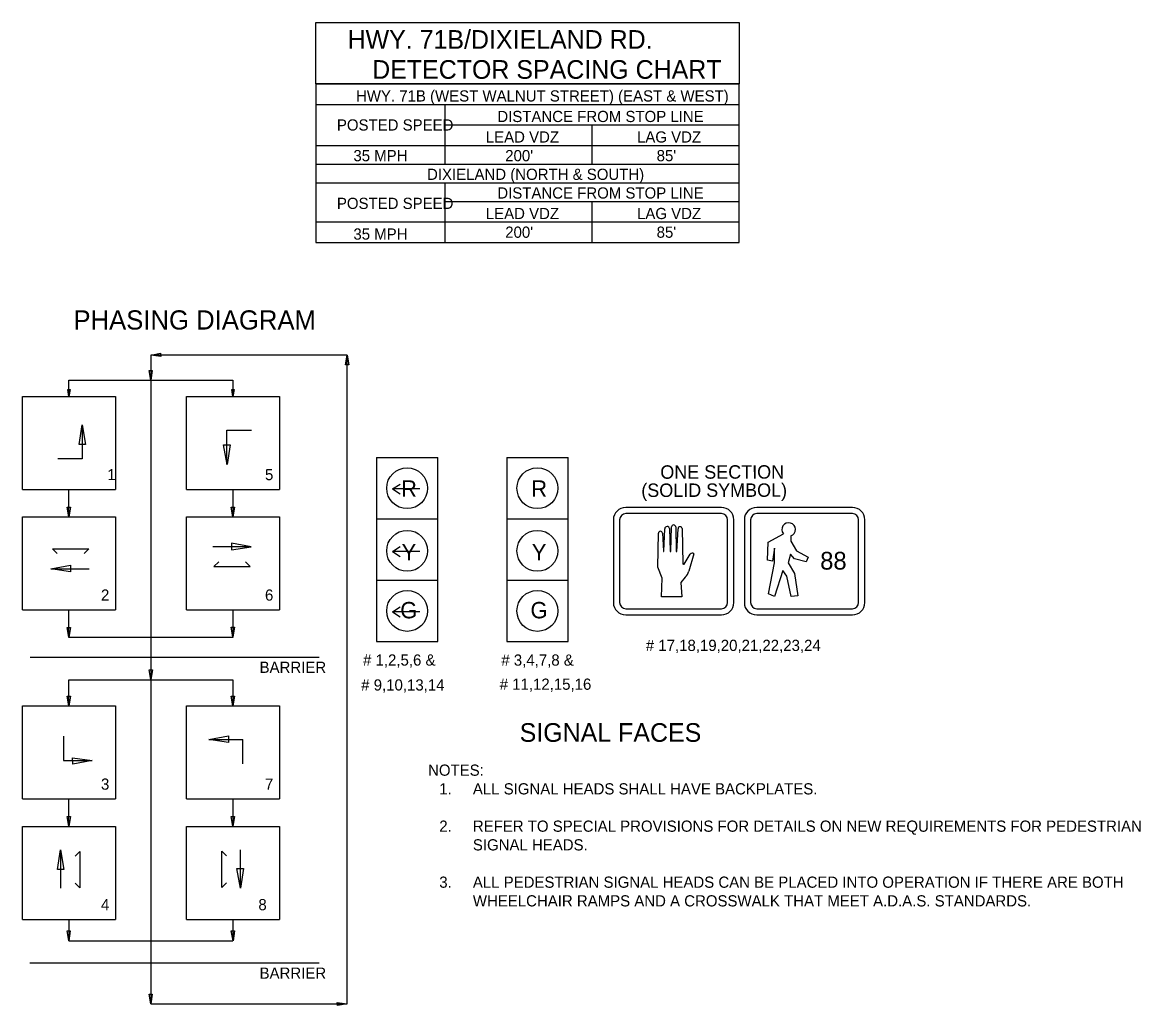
# Model space of a CAD drawing. Extents: x -15.7 to 19.3, y -1.4 to 10.8.
# Drawn here: x -8.42 to -0.43, y 3.54 to 10.56 of the extents above; entities that cross this region are included whole.
import ezdxf

# ---------------------------------------------------------------- set-up
doc = ezdxf.new("R2010")
doc.units = 0
for name, color, linetype in [('$', 7, 'Continuous'), ('base', 7, 'Continuous'), ('PHASE', 7, 'Continuous'), ('T_Drafting', 7, 'Continuous'), ('TBLBDR', 7, 'Continuous'), ('TBLLINE', 7, 'Continuous'), ('TBLTEXT', 7, 'Continuous'), ('TITEXT', 7, 'Continuous')]:
    doc.layers.add(name, color=color, linetype=linetype)

msp = doc.modelspace()

# ---------------------------------------------------------------- linework, layer by layer
at = {"layer": '$'}
for p, q in [((-6.1, 3.5529), (-6.1, 8.1869)), ((-8.0877, 8.0067), (-6.9162, 8.0067)), ((-6.7865, 6.8174), (-7.0596, 6.8174)), ((-8.2155, 6.6601), (-7.9423, 6.6601)), ((-8.1258, 5.4654), (-8.1258, 5.2903)), ((-7.087, 5.4413), (-6.8438, 5.4413)), ((-6.8438, 5.2668), (-6.8438, 5.4413)), ((-8.1258, 5.2903), (-7.9208, 5.2903)), ((-8.0877, 4.156), (-8.0877, 4.0032)), ((-7.5019, 3.8369), (-7.5019, 3.5529)), ((-7.5019, 3.5529), (-6.1, 3.5529))]:
    msp.add_line(p, q, dxfattribs=at)
for points in [[(-6.1, 8.1869), (-7.5019, 8.1869), (-7.5019, 8.0067)], [(-8.0877, 7.8919), (-8.0877, 8.0067)], [(-6.9162, 8.0067), (-6.9162, 7.8919)], [(-7.9921, 7.6882), (-7.9921, 7.4449), (-8.1666, 7.4449)], [(-6.9587, 7.4064), (-6.9587, 7.6496), (-6.7842, 7.6496)], [(-8.0877, 7.0313), (-8.0877, 7.2274)], [(-6.9162, 7.2274), (-6.9162, 7.0313)], [(-6.9162, 6.3668), (-6.9162, 6.1708), (-8.0877, 6.1708), (-8.0877, 6.3668)], [(-7.5019, 6.1708), (-7.5019, 5.8683)], [(-8.0877, 5.6811), (-8.0877, 5.8683), (-6.9162, 5.8683), (-6.9162, 5.6811)], [(-8.0877, 4.8205), (-8.0877, 5.0166)], [(-6.9162, 5.0166), (-6.9162, 4.8205)], [(-8.1485, 4.6534), (-8.1485, 4.3803)], [(-6.8609, 4.3803), (-6.8609, 4.6534)]]:
    msp.add_lwpolyline(points, dxfattribs=at)
at = {"layer": 'PHASE'}
for p, q in [((-5.7765, 7.2306), (-5.7203, 7.2661)), ((-5.5814, 7.2306), (-5.7765, 7.2306)), ((-5.7765, 7.2306), (-5.7203, 7.1951)), ((-5.7765, 6.7833), (-5.7203, 6.8188)), ((-5.5814, 6.7833), (-5.7765, 6.7833)), ((-5.7765, 6.7833), (-5.7203, 6.7479)), ((-5.7765, 6.3539), (-5.7203, 6.3894)), ((-5.5814, 6.3539), (-5.7765, 6.3539)), ((-5.7765, 6.3539), (-5.7203, 6.3185))]:
    msp.add_line(p, q, dxfattribs=at)
for points in [[(-3.7876, 6.7858), (-3.783, 6.9601)], [(-3.7526, 6.9604), (-3.7487, 6.7851)], [(-3.6842, 6.6007), (-3.7158, 6.5618), (-3.7079, 6.4594), (-3.8536, 6.4594), (-3.8485, 6.5934), (-3.8812, 6.6722), (-3.8761, 6.9146)], [(-3.8479, 6.915), (-3.8406, 6.7857)], [(-3.8366, 6.7857), (-3.8309, 6.9468)], [(-3.7965, 6.9479), (-3.792, 6.7857)], [(-3.7445, 6.7851), (-3.7358, 6.9469)], [(-3.7071, 6.9479), (-3.7009, 6.6963)], [(-3.046, 6.462), (-3.0897, 6.4817), (-3.0475, 6.7019), (-3.0457, 6.8071), (-3.0612, 6.7159), (-3.0976, 6.7215), (-3.0915, 6.8514), (-2.9833, 6.91)], [(-2.9291, 6.8949), (-2.93, 6.8585), (-2.8894, 6.7877), (-2.8075, 6.7434), (-2.8195, 6.7105), (-2.9031, 6.7317), (-2.9325, 6.7647), (-2.9504, 6.7022), (-2.9048, 6.6275), (-2.881, 6.4671), (-2.9274, 6.4633), (-2.9579, 6.6086), (-2.9879, 6.648), (-3.046, 6.462)], [(-3.6932, 6.6937), (-3.6483, 6.7659)], [(-3.6223, 6.7664), (-3.6582, 6.6436)]]:
    msp.add_lwpolyline(points, dxfattribs=at)
for centre in [(-5.6711, 7.2361), (-4.7408, 7.2361), (-5.6711, 6.7888), (-4.7408, 6.7888), (-5.6711, 6.3594), (-4.7408, 6.3594)]:
    msp.add_circle(centre, 0.1461, dxfattribs=at)
for centre, radius, start, end in [((-3.8136, 6.9451), 0.0174, 9.19884, 174.46931), ((-3.7678, 6.9586), 0.0153, 6.92087, 174.32546), ((-3.7214, 6.9467), 0.0144, 5.08526, 179.16231), ((-2.9456, 6.9406), 0.0486, 289.8249, 219.00652), ((-3.862, 6.9142), 0.0141, 3.29515, 178.19589), ((-3.8386, 6.7857), 0.00202, 181.1546, 359.79185), ((-3.7898, 6.7857), 0.00218, 181.28856, 2.11272), ((-3.7466, 6.7852), 0.00211, 183.88454, 355.84434), ((-3.6351, 6.7562), 0.0164, 38.81604, 143.75147), ((-3.6965, 6.6966), 0.00439, 183.95836, 317.86458), ((-3.7491, 6.6695), 0.0946, 313.34065, 344.09332)]:
    msp.add_arc(centre, radius, start, end, dxfattribs=at)
at = {"layer": 'TBLBDR'}
for p, q in [((-6.3235, 10.1242), (-6.3235, 8.9912)), ((-6.3235, 10.1242), (-3.2992, 10.1242)), ((-6.3235, 10.1242), (-3.2992, 10.1242)), ((-3.2992, 8.9912), (-3.2992, 10.1242)), ((-6.3235, 9.9776), (-3.2992, 9.9776)), ((-6.3235, 9.551), (-3.2992, 9.551)), ((-6.3235, 9.4177), (-3.2992, 9.4177)), ((-6.3235, 8.9912), (-3.2992, 8.9912)), ((-8.4199, 7.8919), (-7.7554, 7.8919)), ((-8.4199, 7.2274), (-8.4199, 7.8919)), ((-7.7554, 7.8919), (-7.7554, 7.2274)), ((-7.2484, 7.8919), (-6.5839, 7.8919)), ((-7.2484, 7.2274), (-7.2484, 7.8919)), ((-6.5839, 7.8919), (-6.5839, 7.2274)), ((-5.8902, 7.4552), (-5.4519, 7.4552)), ((-5.8902, 7.4552), (-5.8902, 6.1402)), ((-5.4519, 6.1402), (-5.4519, 7.4552)), ((-4.96, 7.4552), (-4.5217, 7.4552)), ((-4.96, 7.4552), (-4.96, 6.1402)), ((-4.5217, 6.1402), (-4.5217, 7.4552)), ((-8.4199, 7.2274), (-7.7554, 7.2274)), ((-7.2484, 7.2274), (-6.5839, 7.2274)), ((-8.4199, 7.0313), (-7.7554, 7.0313)), ((-8.4199, 6.3668), (-8.4199, 7.0313)), ((-7.7554, 7.0313), (-7.7554, 6.3668)), ((-7.2484, 6.3668), (-7.2484, 7.0313)), ((-7.2484, 7.0313), (-6.5839, 7.0313)), ((-6.5839, 7.0313), (-6.5839, 6.3668)), ((-5.8902, 7.0169), (-5.4519, 7.0169)), ((-4.96, 7.0169), (-4.5217, 7.0169)), ((-5.8902, 6.5786), (-5.4519, 6.5786)), ((-4.96, 6.5786), (-4.5217, 6.5786)), ((-8.4199, 6.3668), (-7.7554, 6.3668)), ((-7.2484, 6.3668), (-6.5839, 6.3668)), ((-5.8902, 6.1402), (-5.4519, 6.1402)), ((-4.96, 6.1402), (-4.5217, 6.1402)), ((-8.4199, 5.6811), (-7.7554, 5.6811)), ((-8.4199, 5.0166), (-8.4199, 5.6811)), ((-7.7554, 5.6811), (-7.7554, 5.0166)), ((-7.2484, 5.6811), (-6.5839, 5.6811)), ((-7.2484, 5.0166), (-7.2484, 5.6811)), ((-6.5839, 5.6811), (-6.5839, 5.0166)), ((-8.4199, 5.0166), (-7.7554, 5.0166)), ((-7.2484, 5.0166), (-6.5839, 5.0166)), ((-8.4199, 4.156), (-8.4199, 4.8205)), ((-8.4199, 4.8205), (-7.7554, 4.8205)), ((-7.7554, 4.8205), (-7.7554, 4.156)), ((-7.2484, 4.156), (-7.2484, 4.8205)), ((-7.2484, 4.8205), (-6.5839, 4.8205)), ((-6.5839, 4.8205), (-6.5839, 4.156)), ((-8.4199, 4.156), (-7.7554, 4.156)), ((-7.2484, 4.156), (-6.5839, 4.156))]:
    msp.add_line(p, q, dxfattribs=at)
msp.add_lwpolyline([(-6.3235, 10.5631), (-3.2992, 10.5631), (-3.2992, 10.1242), (-6.3235, 10.1242)], close=True, dxfattribs=at)
for points in [[(-3.4256, 7.0985), (-4.1095, 7.0985)], [(-3.4256, 7.0544), (-4.1095, 7.0544)], [(-2.4901, 7.0985), (-3.174, 7.0985)], [(-2.4901, 7.0544), (-3.174, 7.0544)], [(-4.1977, 7.0104), (-4.1977, 6.4196)], [(-4.1536, 7.0104), (-4.1536, 6.4196)], [(-3.3815, 6.4196), (-3.3815, 7.0104)], [(-3.3374, 6.4196), (-3.3374, 7.0104)], [(-3.2622, 7.0104), (-3.2622, 6.4196)], [(-3.2181, 7.0104), (-3.2181, 6.4196)], [(-2.446, 6.4196), (-2.446, 7.0104)], [(-2.4019, 6.4196), (-2.4019, 7.0104)], [(-4.1095, 6.3755), (-3.4256, 6.3755)], [(-4.1095, 6.3314), (-3.4256, 6.3314)], [(-3.174, 6.3755), (-2.4901, 6.3755)], [(-3.174, 6.3314), (-2.4901, 6.3314)]]:
    msp.add_lwpolyline(points, dxfattribs=at)
for centre, radius, start, end in [((-4.1095, 7.0104), 0.0882, 90, 180), ((-4.1095, 7.0104), 0.0441, 90, 180), ((-3.4256, 7.0104), 0.0882, 360, 90), ((-3.4256, 7.0104), 0.0441, 360, 90), ((-3.174, 7.0104), 0.0882, 90, 180), ((-3.174, 7.0104), 0.0441, 90, 180), ((-2.4901, 7.0104), 0.0882, 360, 90), ((-2.4901, 7.0104), 0.0441, 360, 90), ((-4.1095, 6.4196), 0.0882, 180, 270), ((-4.1095, 6.4196), 0.0441, 180, 270), ((-3.4256, 6.4196), 0.0882, 270, 360), ((-3.4256, 6.4196), 0.0441, 270, 360), ((-3.174, 6.4196), 0.0882, 180, 270), ((-3.174, 6.4196), 0.0441, 180, 270), ((-2.4901, 6.4196), 0.0882, 270, 360), ((-2.4901, 6.4196), 0.0441, 270, 360)]:
    msp.add_arc(centre, radius, start, end, dxfattribs=at)
at = {"layer": 'TBLLINE'}
for p, q in [((-5.4016, 9.9776), (-5.4016, 9.551)), ((-5.4016, 9.8309), (-3.2992, 9.8309)), ((-4.3504, 9.551), (-4.3504, 9.8309)), ((-6.3235, 9.6843), (-3.2992, 9.6843)), ((-5.4016, 9.4177), (-5.4016, 8.9912)), ((-5.4016, 9.2844), (-4.3504, 9.2844)), ((-4.3504, 9.2844), (-3.2992, 9.2844)), ((-4.3504, 8.9912), (-4.3504, 9.2844)), ((-6.3235, 9.1378), (-3.2992, 9.1378))]:
    msp.add_line(p, q, dxfattribs=at)
at = {"layer": 'TITEXT'}
for p, q in [((-8.3653, 6.0291), (-6.2994, 6.0291)), ((-6.9162, 4.156), (-6.9162, 4.0032)), ((-8.0877, 4.0032), (-6.9162, 4.0032)), ((-6.2994, 3.8446), (-8.3673, 3.8446))]:
    msp.add_line(p, q, dxfattribs=at)
for points in [[(-7.4321, 8.1998), (-7.4317, 8.1764), (-7.5019, 8.1869)], [(-6.0871, 8.117), (-6.1104, 8.1166), (-6.1, 8.1869)], [(-7.5148, 8.0766), (-7.4915, 8.077), (-7.5019, 8.0067)], [(-8.0959, 7.9409), (-8.0795, 7.9409), (-8.0877, 7.8919)], [(-6.9243, 7.9409), (-6.908, 7.9409), (-6.9162, 7.8919)], [(-7.9679, 7.5491), (-8.0146, 7.5482), (-7.9937, 7.6887)], [(-6.9828, 7.5455), (-6.9362, 7.5463), (-6.957, 7.4059)], [(-8.0994, 7.1014), (-8.076, 7.1014), (-8.0877, 7.0313)], [(-6.9278, 7.1014), (-6.9045, 7.1014), (-6.9162, 7.0313)], [(-6.9261, 6.8432), (-6.927, 6.7965), (-6.7865, 6.8174)], [(-8.0758, 6.6859), (-8.075, 6.6393), (-8.2155, 6.6601)], [(-8.0994, 6.2424), (-8.076, 6.2424), (-8.0877, 6.1724)], [(-6.9278, 6.244), (-6.9045, 6.244), (-6.9162, 6.174)], [(-7.5147, 5.9381), (-7.4914, 5.9385), (-7.5018, 5.8683)], [(-8.0994, 5.7511), (-8.076, 5.7511), (-8.0877, 5.6811)], [(-6.9278, 5.7511), (-6.9045, 5.7511), (-6.9162, 5.6811)], [(-6.9474, 5.4671), (-6.9466, 5.4204), (-7.087, 5.4413)], [(-8.0604, 5.2645), (-8.0612, 5.3112), (-7.9208, 5.2903)], [(-8.0994, 4.8906), (-8.076, 4.8906), (-8.0877, 4.8205)], [(-6.9278, 4.8906), (-6.9045, 4.8906), (-6.9162, 4.8205)], [(-8.1227, 4.5137), (-8.1694, 4.5129), (-8.1485, 4.6534)], [(-6.8867, 4.5199), (-6.84, 4.5207), (-6.8609, 4.3803)], [(-8.1006, 4.0738), (-8.0773, 4.0742), (-8.0877, 4.004)], [(-6.9278, 4.0738), (-6.9045, 4.0742), (-6.9149, 4.004)], [(-7.5148, 3.6227), (-7.4915, 3.6231), (-7.5019, 3.5529)], [(-6.1697, 3.5406), (-6.1702, 3.564), (-6.0999, 3.5535)]]:
    msp.add_lwpolyline(points, close=True, dxfattribs=at)
for points in [[(-7.5019, 8.0067), (-7.5019, 5.9665)], [(-8.1702, 6.77), (-8.2039, 6.8036), (-7.9454, 6.8036), (-7.979, 6.77)], [(-7.0174, 6.7102), (-7.051, 6.6766), (-6.7926, 6.6766), (-6.8262, 6.7102)], [(-7.5019, 5.8683), (-7.5019, 3.8369)], [(-8.0422, 4.6073), (-8.0085, 4.6409), (-8.0085, 4.3825), (-8.0422, 4.4161)], [(-6.9624, 4.4183), (-6.996, 4.3847), (-6.996, 4.6432), (-6.9624, 4.6095)]]:
    msp.add_lwpolyline(points, dxfattribs=at)

# ---------------------------------------------------------------- texts
at = {"layer": '$'}
for s, height, p in [('HWY. 71B/DIXIELAND RD.', 0.13332, (-6.0969, 10.3744)), ('PHASING DIAGRAM', 0.137143, (-8.0551, 8.3693))]:
    msp.add_text(s, height=height, dxfattribs=at).set_placement(p)
at = {"layer": 'base'}
for s, height, p in [('DETECTOR SPACING CHART', 0.13332, (-5.9211, 10.1601)), ('SIGNAL FACES', 0.1333, (-4.8674, 5.4247))]:
    msp.add_text(s, height=height, dxfattribs=at).set_placement(p)
at = {"layer": 'T_Drafting'}
for s, p in [('ONE SECTION', (-3.8625, 7.3035)), ('(SOLID SYMBOL)', (-3.9985, 7.1733))]:
    msp.add_text(s, height=0.096, rotation=0.07203, dxfattribs=at).set_placement(p)
at = {"layer": 'TBLTEXT'}
for s, height, p in [('HWY. 71B (WEST WALNUT STREET) (EAST & WEST)', 0.079992, (-6.0364, 9.9978)), ('DISTANCE FROM STOP LINE', 0.079992, (-5.0269, 9.8512)), ('POSTED SPEED', 0.079992, (-6.1729, 9.7904)), ('LEAD VDZ', 0.07999, (-5.1091, 9.7046)), ('LAG VDZ', 0.07999, (-4.029, 9.7046)), ('35 MPH', 0.07999, (-6.055, 9.5713)), ("200'", 0.07999, (-4.9705, 9.5713)), ("85'", 0.07999, (-3.8888, 9.5713)), ('DIXIELAND (NORTH & SOUTH)', 0.079992, (-5.529, 9.438)), ('DISTANCE FROM STOP LINE', 0.079992, (-5.0269, 9.3047)), ('POSTED SPEED', 0.079992, (-6.1729, 9.2305)), ('LEAD VDZ', 0.07999, (-5.1091, 9.1581)), ('LAG VDZ', 0.07999, (-4.029, 9.1581)), ('35 MPH', 0.07999, (-6.055, 9.0114)), ("200'", 0.07999, (-4.9705, 9.0247)), ("85'", 0.07999, (-3.8888, 9.0247)), ('1', 0.08, (-7.8126, 7.2935)), ('5', 0.08, (-6.6867, 7.2935)), ('R', 0.1169, (-5.7144, 7.1751)), ('R', 0.1169, (-4.7842, 7.1751)), ('Y', 0.1169, (-5.7108, 6.7205)), ('Y', 0.1169, (-4.7806, 6.7205)), ('88', 0.12694, (-2.7204, 6.6547)), ('2', 0.08, (-7.8583, 6.4329)), ('6', 0.08, (-6.6867, 6.4329)), ('G', 0.1169, (-5.7202, 6.3067)), ('G', 0.1169, (-4.7899, 6.3067)), ('# 17,18,19,20,21,22,23,24', 0.08, (-3.9658, 6.0736)), ('BARRIER', 0.08, (-6.7253, 5.9172)), ('# 1,2,5,6 &', 0.08, (-5.986, 5.9691)), ('# 3,4,7,8 &', 0.08, (-4.9981, 5.9686)), ('# 9,10,13,14', 0.08, (-5.9992, 5.791)), ('# 11,12,15,16', 0.08, (-5.0098, 5.7965)), ('NOTES:', 0.08, (-5.5216, 5.1824)), ('3', 0.08, (-7.8583, 5.0827)), ('7', 0.08, (-6.6867, 5.0827)), ('1.', 0.08, (-5.4416, 5.049)), ('ALL SIGNAL HEADS SHALL HAVE BACKPLATES.', 0.08, (-5.2016, 5.049)), ('2.', 0.08, (-5.4416, 4.7824)), ('REFER TO SPECIAL PROVISIONS FOR DETAILS ON NEW REQUIREMENTS FOR PEDESTRIAN', 0.08, (-5.2016, 4.7824)), ('SIGNAL HEADS.', 0.08, (-5.2016, 4.649)), ('3.', 0.08, (-5.4416, 4.3824)), ('ALL PEDESTRIAN SIGNAL HEADS CAN BE PLACED INTO OPERATION IF THERE ARE BOTH', 0.08, (-5.2016, 4.3824)), ('WHEELCHAIR RAMPS AND A CROSSWALK THAT MEET A.D.A.S. STANDARDS.', 0.08, (-5.2016, 4.249)), ('4', 0.08, (-7.8583, 4.2221)), ('8', 0.08, (-6.7338, 4.2221)), ('BARRIER', 0.08, (-6.7253, 3.7328))]:
    msp.add_text(s, height=height, dxfattribs=at).set_placement(p)

doc.saveas('drawing.dxf')
